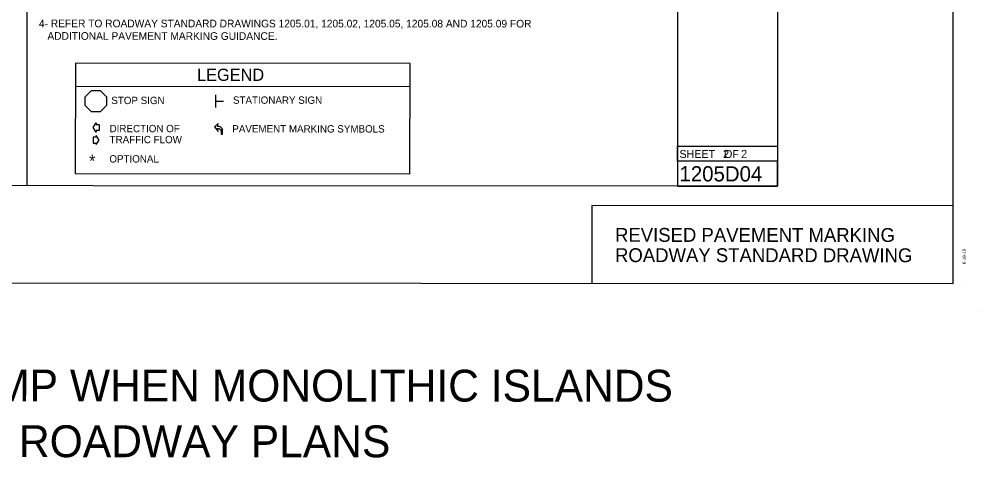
# Model space of a CAD drawing. Extents: x 50667 to 52386, y 46650 to 50479.
# Drawn here: x 51455 to 52360, y 46650 to 47063 of the extents above; entities that cross this region are included whole.
import ezdxf

# ---------------------------------------------------------------- set-up
doc = ezdxf.new("R2010")
doc.units = 0
for name, color, linetype in [('Default', 7, 'Continuous'), ('DEV TUBULAR MARKER SECTIONAL VIEW CELL', 7, 'Continuous'), ('Exist Guardrail Text', 7, 'Continuous'), ('Exist Right of Way Monument Text', 7, 'Continuous'), ('Gray Area Fill Shapes', 7, 'Continuous'), ('Prop SBG', 7, 'Continuous'), ('Sheet Sticker Preliminary CELL', 7, 'Continuous'), ('TSCONFLICT', 7, 'Continuous')]:
    doc.layers.add(name, color=color, linetype=linetype)

msp = doc.modelspace()

# ---------------------------------------------------------------- linework, layer by layer
at = {"layer": 'Default'}
for p, q in [((51462.45, 47676.12), (51462.09, 46906.44)), ((51507.74, 47021.98), (51507.7, 46918.01)), ((51823.19, 47021.83), (51507.74, 47021.98)), ((51823.14, 46917.86), (51823.19, 47021.83)), ((51823.18, 46999.86), (51507.73, 47000.01)), ((51517.09, 46990.39), (51522.94, 46996.24)), ((51517.09, 46982.1), (51517.09, 46990.39)), ((51522.94, 46996.24), (51531.23, 46996.23)), ((51531.23, 46996.23), (51537.12, 46990.38)), ((51537.12, 46990.38), (51537.12, 46982.09)), ((51522.93, 46976.25), (51517.09, 46982.1)), ((51537.12, 46982.09), (51531.22, 46976.25)), ((51531.22, 46976.25), (51522.93, 46976.25)), ((51507.7, 46918.01), (51823.14, 46917.86))]:
    msp.add_line(p, q, dxfattribs=at)
at = {"layer": 'DEV TUBULAR MARKER SECTIONAL VIEW CELL'}
msp.add_lwpolyline([(50879.23, 46906.71), (50879.58, 47676.39), (52169.91, 47675.79), (52169.55, 46906.11)], close=True, dxfattribs=at)
at = {"layer": 'Exist Guardrail Text'}
for p, q in [((51639.75, 46992.04), (51639.74, 46980.4)), ((51639.75, 46986.17), (51647.29, 46986.17))]:
    msp.add_line(p, q, dxfattribs=at)
at = {"layer": 'Exist Right of Way Monument Text'}
for p, q in [((52346.28, 46813.11), (52346.28, 46813.11)), ((52360.19, 46789.55), (52360.19, 46789.55))]:
    msp.add_line(p, q, dxfattribs=at)
msp.add_lwpolyline([(52335.61, 47869.9), (50830.4, 47870.6), (50829.91, 46815.38), (52335.12, 46814.68)], close=True, dxfattribs=at)
at = {"layer": 'Gray Area Fill Shapes'}
for points in [[(51530.26, 46958.6), (51527.39, 46958.6), (51527.39, 46957.16), (51524.51, 46961.53), (51527.39, 46965.79), (51527.39, 46964.35), (51530.26, 46964.35)], [(51524.47, 46946.73), (51527.35, 46946.73), (51527.34, 46945.29), (51530.22, 46949.65), (51527.35, 46953.92), (51527.35, 46952.48), (51524.47, 46952.48)]]:
    msp.add_lwpolyline(points, close=True, dxfattribs=at)
at = {"layer": 'Prop SBG'}
for points in [[(51645.3, 46955.22), (51646.54, 46955.22), (51646.54, 46958.44), (51646.51, 46959.03), (51646.43, 46959.48), (51646.28, 46959.97), (51646.06, 46960.39), (51645.85, 46960.7), (51645.49, 46961.11), (51645.18, 46961.39), (51644.81, 46961.68), (51644.32, 46961.97), (51643.92, 46962.13), (51643.39, 46962.29), (51642.67, 46962.39), (51641.67, 46962.39), (51642.5, 46965.19), (51638.97, 46961.97), (51642.29, 46957.61), (51641.66, 46960.41), (51642.5, 46960.41), (51642.96, 46960.39), (51643.39, 46960.27), (51643.73, 46960.11), (51644.16, 46959.86), (51644.45, 46959.62), (51644.78, 46959.21), (51645.02, 46958.74), (51645.2, 46958.27), (51645.3, 46957.61)], [(51645.3, 46955.22), (51646.54, 46955.22), (51646.54, 46958.44), (51646.51, 46959.03), (51646.43, 46959.48), (51646.28, 46959.97), (51646.06, 46960.38), (51645.84, 46960.7), (51645.49, 46961.11), (51645.18, 46961.39), (51644.8, 46961.68), (51644.31, 46961.97), (51643.92, 46962.13), (51643.39, 46962.29), (51642.67, 46962.39), (51641.67, 46962.39), (51642.5, 46965.19), (51638.97, 46961.97), (51642.29, 46957.61), (51641.66, 46960.41), (51642.49, 46960.41), (51642.96, 46960.39), (51643.39, 46960.27), (51643.73, 46960.11), (51644.16, 46959.86), (51644.45, 46959.62), (51644.78, 46959.21), (51645.02, 46958.74), (51645.2, 46958.27), (51645.3, 46957.61)]]:
    msp.add_lwpolyline(points, close=True, dxfattribs=at)
at = {"layer": 'Sheet Sticker Preliminary CELL'}
msp.add_lwpolyline([(52075.51, 47444.92), (52169.8, 47444.88), (52169.91, 47675.79), (52075.61, 47675.83), (52075.26, 46906.16), (52169.55, 46906.11), (52169.57, 46929.69), (52075.27, 46929.73), (52075.27, 46943.87), (52169.57, 46943.82)], dxfattribs=at)
at = {"layer": 'TSCONFLICT'}
msp.add_lwpolyline([(51994.64, 46814.84), (52335.12, 46814.68), (52335.15, 46887.82), (51994.67, 46887.98)], close=True, dxfattribs=at)

# ---------------------------------------------------------------- texts
at = {"layer": 'Default'}
for s, height, p in [('4- REFER TO ROADWAY STANDARD DRAWINGS 1205.01, 1205.02, 1205.05, 1205.08 AND 1205.09 FOR', 7.1874, (51473.42, 47055.82)), ('   ADDITIONAL PAVEMENT MARKING GUIDANCE.', 7.1874, (51473.41, 47044.03)), ('LEGEND', 11.5, (51622.46, 47005.34)), ('STOP SIGN', 6.9, (51541.62, 46983.48)), ('STATIONARY SIGN', 6.8999, (51656.31, 46983.77)), ('DIRECTION OF', 6.8999, (51540.03, 46957)), ('PAVEMENT MARKING SYMBOLS', 6.8999, (51655.71, 46956.76)), ('TRAFFIC FLOW', 6.8999, (51540.02, 46946.65)), ('*', 11.5, (51520.73, 46924.23)), ('OPTIONAL', 6.9, (51539.82, 46928.48)), ('REVISED PAVEMENT MARKING', 13.0513, (52016.41, 46853.81)), ('ROADWAY STANDARD DRAWING', 13.0513, (52016.4, 46834.73)), ('INCLUDE THIS SHEET WITH PMP WHEN MONOLITHIC ISLANDS', 30, (50856.21, 46703.84)), (' ARE IN THE ROADWAY PLANS', 30, (51207.2, 46651.18))]:
    msp.add_text(s, height=height, rotation=359.97341, dxfattribs=at).set_placement(p)
at = {"layer": 'DEV TUBULAR MARKER SECTIONAL VIEW CELL'}
for s, height, rotation, p in [('2    2', 7.667, 359.97341, (52118.15, 46932.68)), ('1205D04', 14.375, 359.97341, (52077.17, 46910.66)), ('6-18-19', 3.012, 89.97341, (52346.94, 46832.78))]:
    msp.add_text(s, height=height, rotation=rotation, dxfattribs=at).set_placement(p)
at = {"layer": 'Sheet Sticker Preliminary CELL'}
msp.add_text('SHEET   OF', height=7.542, rotation=359.97341, dxfattribs=at).set_placement((52077.14, 46932.75))

doc.saveas('drawing.dxf')
